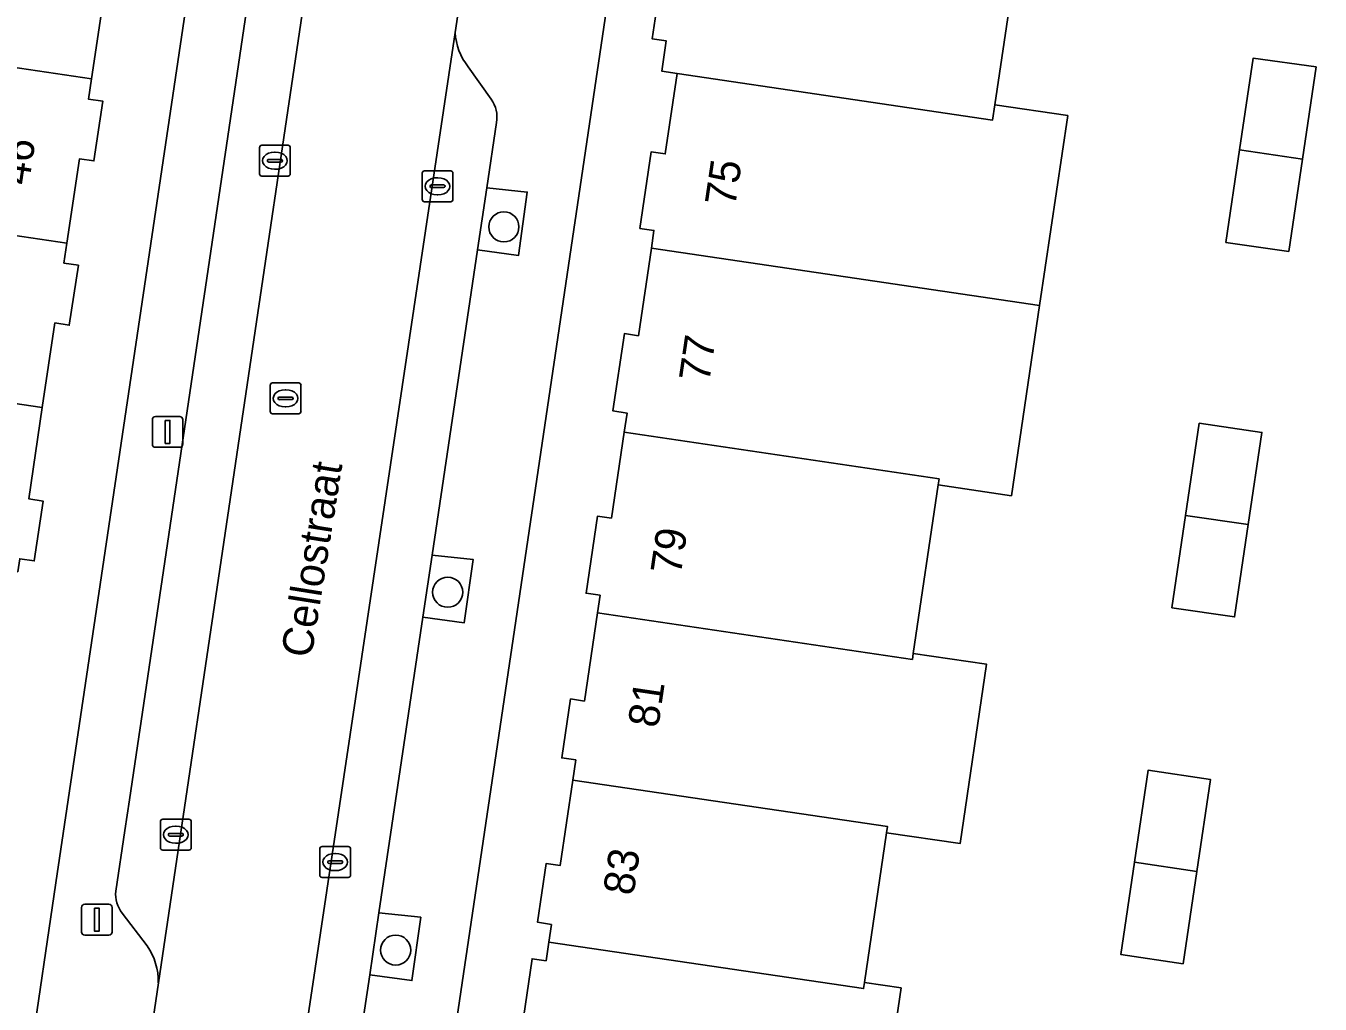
# Model space of a CAD drawing. Extents: x 164148 to 165261, y 382513 to 383432.
# Drawn here: x 164386.93 to 164428.99, y 382927.78 to 382959.57 of the extents above; entities that cross this region are included whole.
import ezdxf

# ---------------------------------------------------------------- set-up
doc = ezdxf.new("R2010")
doc.units = 0
for name, color, linetype in [('IMGEO_Boom', 7, 'Continuous'), ('IMGEO_Erf', 7, 'Continuous'), ('IMGEO_Groenvoorziening', 7, 'Continuous'), ('IMGEO_Kolk', 7, 'Continuous'), ('IMGEO_Lichtmast', 7, 'Continuous'), ('IMGEO_Openbare_ruimte_label', 7, 'Continuous'), ('IMGEO_Pand', 7, 'Continuous'), ('IMGEO_Pand_nummerreeks', 7, 'Continuous'), ('IMGEO_Parkeervlak_open', 7, 'Continuous'), ('IMGEO_Rijbaan_lokaal_open', 7, 'Continuous'), ('IMGEO_Rioolput', 7, 'Continuous'), ('IMGEO_Voetpad_open', 7, 'Continuous')]:
    doc.layers.add(name, color=color, linetype=linetype)

msp = doc.modelspace()

# ---------------------------------------------------------------- linework, layer by layer
at = {"layer": 'IMGEO_Boom'}
for centre in [(164402.46, 382953.036), (164400.635, 382941.165), (164398.944, 382929.538)]:
    msp.add_circle(centre, 0.489, dxfattribs=at)
at = {"layer": 'IMGEO_Erf'}
for points in [[(164386.768, 382924.065), (164387.061, 382926.045), (164387.902, 382931.724), (164393.467, 382969.194), (164386.248, 382970.282)], [(164385.848, 382967.079), (164390.338, 382966.42), (164389.758, 382962.536), (164390.227, 382962.469), (164389.942, 382960.525), (164389.467, 382960.594), (164389.057, 382957.848), (164388.959, 382957.188), (164389.428, 382957.119), (164389.14, 382955.178), (164388.669, 382955.248), (164388.259, 382952.508), (164388.162, 382951.861), (164388.632, 382951.789), (164388.334, 382949.842), (164387.872, 382949.916), (164387.461, 382947.169), (164387.018, 382944.201), (164387.488, 382944.128), (164387.199, 382942.18), (164386.727, 382942.253)], [(164419.288, 382962.906), (164418.415, 382957.004), (164420.787, 382956.653), (164419.872, 382950.476), (164418.957, 382944.298), (164416.574, 382944.65), (164415.764, 382939.179), (164418.147, 382938.826), (164417.284, 382932.998), (164414.9, 382933.351), (164414.179, 382928.484), (164415.369, 382928.308), (164414.544, 382922.733)], [(164403.093, 382927.341), (164403.379, 382929.257), (164403.833, 382929.19), (164403.923, 382929.8), (164404.006, 382930.366), (164403.553, 382930.447), (164403.838, 382932.357), (164404.291, 382932.291), (164404.7, 382935.064), (164404.796, 382935.716), (164404.343, 382935.784), (164404.628, 382937.7), (164405.079, 382937.631), (164405.503, 382940.497), (164405.587, 382941.066), (164405.132, 382941.132), (164405.507, 382943.641), (164405.957, 382943.574), (164406.37, 382946.365), (164406.462, 382946.988), (164406.006, 382947.057), (164406.38, 382949.567), (164406.833, 382949.501), (164407.253, 382952.345), (164407.338, 382952.921), (164406.884, 382952.988), (164407.25, 382955.475), (164407.705, 382955.408), (164408.091, 382958.021), (164407.589, 382958.097), (164407.736, 382959.075), (164407.281, 382959.143), (164407.67, 382961.751)]]:
    msp.add_lwpolyline(points, dxfattribs=at)
for points in [[(164455.128, 382958.161), (164406.562, 382965.305), (164395.217, 382888.733), (164443.704, 382881.759), (164444.09, 382883.266), (164444.484, 382885.938)], [(164425.925, 382952.531), (164426.369, 382955.541), (164426.808, 382958.517), (164428.857, 382958.234), (164428.412, 382955.238), (164427.968, 382952.241)], [(164426.651, 382943.361), (164426.207, 382940.363), (164424.173, 382940.661), (164424.616, 382943.662), (164425.058, 382946.655), (164427.096, 382946.358)], [(164422.511, 382929.391), (164422.953, 382932.391), (164423.394, 382935.382), (164425.424, 382935.085), (164424.98, 382932.091), (164424.535, 382929.096)]]:
    msp.add_lwpolyline(points, close=True, dxfattribs=at)
at = {"layer": 'IMGEO_Groenvoorziening'}
for points in [[(164401.902, 382954.305), (164401.602, 382952.29), (164402.936, 382952.107), (164403.221, 382954.164)], [(164400.128, 382942.373), (164399.829, 382940.36), (164401.173, 382940.175), (164401.458, 382942.232)], [(164398.4, 382930.752), (164398.1, 382928.736), (164399.474, 382928.549), (164399.759, 382930.606)]]:
    msp.add_lwpolyline(points, close=True, dxfattribs=at)
at = {"layer": 'IMGEO_Kolk'}
for p, q in [((164394.519, 382954.76), (164394.519, 382955.612)), ((164394.594, 382955.686), (164395.446, 382955.686)), ((164395.52, 382955.612), (164395.52, 382954.76)), ((164394.778, 382955.18), (164394.778, 382955.192)), ((164395.216, 382955.143), (164394.818, 382955.143)), ((164394.821, 382955.229), (164395.219, 382955.229)), ((164395.007, 382955.466), (164395.032, 382955.466)), ((164395.262, 382955.192), (164395.262, 382955.18)), ((164395.446, 382954.686), (164394.594, 382954.686)), ((164395.03, 382954.906), (164395.005, 382954.906)), ((164399.805, 382953.928), (164399.805, 382954.78)), ((164399.88, 382954.854), (164400.732, 382954.854)), ((164400.293, 382954.634), (164400.318, 382954.634)), ((164400.806, 382954.78), (164400.806, 382953.928)), ((164400.064, 382954.348), (164400.064, 382954.36)), ((164400.502, 382954.311), (164400.104, 382954.311)), ((164400.107, 382954.397), (164400.505, 382954.397)), ((164400.548, 382954.36), (164400.548, 382954.348)), ((164400.732, 382953.854), (164399.88, 382953.854)), ((164400.316, 382954.074), (164400.291, 382954.074)), ((164391.298, 382932.862), (164391.298, 382933.714)), ((164391.373, 382933.788), (164392.225, 382933.788)), ((164392.299, 382933.714), (164392.299, 382932.862)), ((164391.557, 382933.282), (164391.557, 382933.294)), ((164391.995, 382933.245), (164391.597, 382933.245)), ((164391.6, 382933.331), (164391.998, 382933.331)), ((164391.786, 382933.568), (164391.811, 382933.568)), ((164392.041, 382933.294), (164392.041, 382933.282)), ((164392.225, 382932.788), (164391.373, 382932.788)), ((164391.809, 382933.008), (164391.784, 382933.008)), ((164396.477, 382931.973), (164396.477, 382932.825)), ((164396.552, 382932.899), (164397.404, 382932.899)), ((164397.478, 382932.825), (164397.478, 382931.973)), ((164396.736, 382932.393), (164396.736, 382932.405)), ((164397.174, 382932.356), (164396.776, 382932.356)), ((164396.779, 382932.442), (164397.177, 382932.442)), ((164396.965, 382932.679), (164396.99, 382932.679)), ((164397.22, 382932.405), (164397.22, 382932.393)), ((164396.988, 382932.119), (164396.963, 382932.119)), ((164397.404, 382931.899), (164396.552, 382931.899))]:
    msp.add_line(p, q, dxfattribs=at)
for points in [[(164394.519, 382954.76), (164394.519, 382955.612)], [(164394.594, 382955.686), (164395.446, 382955.686)], [(164395.52, 382955.612), (164395.52, 382954.76)], [(164395.446, 382954.686), (164394.594, 382954.686)], [(164399.805, 382953.928), (164399.805, 382954.78)], [(164399.88, 382954.854), (164400.732, 382954.854)], [(164400.806, 382954.78), (164400.806, 382953.928)], [(164400.732, 382953.854), (164399.88, 382953.854)], [(164391.298, 382932.862), (164391.298, 382933.714)], [(164391.373, 382933.788), (164392.225, 382933.788)], [(164392.299, 382933.714), (164392.299, 382932.862)], [(164392.225, 382932.788), (164391.373, 382932.788)], [(164396.477, 382931.973), (164396.477, 382932.825)], [(164396.552, 382932.899), (164397.404, 382932.899)], [(164397.478, 382932.825), (164397.478, 382931.973)], [(164397.404, 382931.899), (164396.552, 382931.899)]]:
    msp.add_lwpolyline(points, dxfattribs=at)
for centre, radius, start, end in [((164394.596, 382955.61), 0.0765, 91.552, 178.448), ((164394.596, 382955.61), 0.0765, 91.552, 178.448), ((164395.444, 382955.61), 0.0765, 1.552, 88.448), ((164395.444, 382955.61), 0.0765, 1.552, 88.448), ((164394.818, 382955.189), 0.0403, 85.8775, 175.7526), ((164394.815, 382955.179), 0.0366, 178.938, 274.7102), ((164395.219, 382955.186), 0.043, 264.8664, 352.4533), ((164395.223, 382955.191), 0.0386, 1.7309, 96.639), ((164394.596, 382954.762), 0.0765, 181.552, 268.448), ((164394.596, 382954.762), 0.0765, 181.552, 268.448), ((164395.444, 382954.762), 0.0765, 271.552, 358.448), ((164395.444, 382954.762), 0.0765, 271.552, 358.448), ((164399.882, 382954.778), 0.0765, 91.552, 178.448), ((164399.882, 382954.778), 0.0765, 91.552, 178.448), ((164400.73, 382954.778), 0.0765, 1.552, 88.448), ((164400.73, 382954.778), 0.0765, 1.552, 88.448), ((164400.104, 382954.357), 0.0403, 85.8775, 175.7526), ((164400.101, 382954.347), 0.0366, 178.938, 274.7102), ((164400.505, 382954.354), 0.043, 264.8664, 352.4533), ((164400.509, 382954.359), 0.0386, 1.7309, 96.639), ((164399.882, 382953.93), 0.0765, 181.552, 268.448), ((164399.882, 382953.93), 0.0765, 181.552, 268.448), ((164400.73, 382953.93), 0.0765, 271.552, 358.448), ((164400.73, 382953.93), 0.0765, 271.552, 358.448), ((164391.375, 382933.712), 0.0765, 91.552, 178.448), ((164391.375, 382933.712), 0.0765, 91.552, 178.448), ((164392.223, 382933.712), 0.0765, 1.552, 88.448), ((164392.223, 382933.712), 0.0765, 1.552, 88.448), ((164391.597, 382933.291), 0.0403, 85.8775, 175.7526), ((164391.594, 382933.281), 0.0366, 178.938, 274.7102), ((164391.998, 382933.288), 0.043, 264.8664, 352.4533), ((164392.002, 382933.293), 0.0386, 1.7309, 96.639), ((164391.375, 382932.864), 0.0765, 181.552, 268.448), ((164391.375, 382932.864), 0.0765, 181.552, 268.448), ((164392.223, 382932.864), 0.0765, 271.552, 358.448), ((164392.223, 382932.864), 0.0765, 271.552, 358.448), ((164396.554, 382932.823), 0.0765, 91.552, 178.448), ((164396.554, 382932.823), 0.0765, 91.552, 178.448), ((164397.402, 382932.823), 0.0765, 1.552, 88.448), ((164397.402, 382932.823), 0.0765, 1.552, 88.448), ((164396.776, 382932.402), 0.0403, 85.8775, 175.7526), ((164396.773, 382932.392), 0.0366, 178.938, 274.7102), ((164397.177, 382932.399), 0.043, 264.8664, 352.4533), ((164397.181, 382932.404), 0.0386, 1.7309, 96.639), ((164396.554, 382931.975), 0.0765, 181.552, 268.448), ((164396.554, 382931.975), 0.0765, 181.552, 268.448), ((164397.402, 382931.975), 0.0765, 271.552, 358.448), ((164397.402, 382931.975), 0.0765, 271.552, 358.448)]:
    msp.add_arc(centre, radius, start, end, dxfattribs=at)
for centre, major_axis, ratio, start_param, end_param in [((164395.006, 382955.186), (-0.387, 0.002), 0.722429, 4.712389, 7.853982), ((164395.031, 382955.186), (-0.39, 0.002), 0.717154, 1.570796, 4.712389), ((164400.292, 382954.354), (-0.387, 0.002), 0.722429, 4.712389, 7.853982), ((164400.317, 382954.354), (-0.39, 0.002), 0.717154, 1.570796, 4.712389), ((164391.785, 382933.288), (-0.387, 0.002), 0.722429, 4.712389, 7.853982), ((164391.81, 382933.288), (-0.39, 0.002), 0.717154, 1.570796, 4.712389), ((164396.964, 382932.399), (-0.387, 0.002), 0.722429, 4.712389, 7.853982), ((164396.989, 382932.399), (-0.39, 0.002), 0.717154, 1.570796, 4.712389)]:
    msp.add_ellipse(centre, major_axis=major_axis, ratio=ratio, start_param=start_param, end_param=end_param, dxfattribs=at)
at = {"layer": 'IMGEO_Lichtmast'}
for p, q in [((164391.038, 382945.973), (164391.038, 382946.773)), ((164391.038, 382946.773), (164391.038, 382945.973)), ((164391.138, 382946.873), (164391.928, 382946.873)), ((164391.928, 382946.873), (164391.138, 382946.873)), ((164392.028, 382946.773), (164392.028, 382945.973)), ((164392.028, 382945.973), (164392.028, 382946.773)), ((164391.928, 382945.873), (164391.138, 382945.873)), ((164391.138, 382945.873), (164391.928, 382945.873)), ((164388.737, 382930.126), (164388.737, 382930.926)), ((164388.737, 382930.926), (164388.737, 382930.126)), ((164388.837, 382931.026), (164389.627, 382931.026)), ((164389.627, 382931.026), (164388.837, 382931.026)), ((164389.727, 382930.926), (164389.727, 382930.126)), ((164389.727, 382930.126), (164389.727, 382930.926)), ((164389.627, 382930.026), (164388.837, 382930.026)), ((164388.837, 382930.026), (164389.627, 382930.026))]:
    msp.add_line(p, q, dxfattribs=at)
for points in [[(164391.458, 382946.748), (164391.608, 382946.748), (164391.608, 382945.998), (164391.458, 382945.998), (164391.458, 382946.748)], [(164389.157, 382930.901), (164389.307, 382930.901), (164389.307, 382930.151), (164389.157, 382930.151), (164389.157, 382930.901)]]:
    msp.add_lwpolyline(points, dxfattribs=at)
for centre, start, end in [((164391.138, 382946.773), 90, 180), ((164391.138, 382946.773), 90, 180), ((164391.928, 382946.773), 0, 90), ((164391.928, 382946.773), 360, 90), ((164391.138, 382945.973), 180, 270), ((164391.138, 382945.973), 180, 270), ((164391.928, 382945.973), 270, 0), ((164391.928, 382945.973), 270, 0), ((164388.837, 382930.926), 90, 180), ((164388.837, 382930.926), 90, 180), ((164389.627, 382930.926), 0, 90), ((164389.627, 382930.926), 360, 90), ((164388.837, 382930.126), 180, 270), ((164388.837, 382930.126), 180, 270), ((164389.627, 382930.126), 270, 0), ((164389.627, 382930.126), 270, 0)]:
    msp.add_arc(centre, 0.1, start, end, dxfattribs=at)
at = {"layer": 'IMGEO_Pand'}
for points in [[(164389.758, 382962.536), (164390.338, 382966.42), (164385.848, 382967.079), (164385.387, 382963.963), (164384.358, 382964.12), (164379.624, 382964.842), (164378.809, 382959.364), (164389.057, 382957.848), (164389.467, 382960.594), (164389.942, 382960.525), (164390.227, 382962.469)], [(164419.288, 382962.906), (164408.545, 382964.496), (164408.125, 382961.681), (164407.67, 382961.751), (164407.281, 382959.143), (164407.736, 382959.075), (164407.589, 382958.097), (164408.091, 382958.021), (164418.341, 382956.503), (164418.415, 382957.004)], [(164389.428, 382957.119), (164388.959, 382957.188), (164389.057, 382957.848), (164378.809, 382959.364), (164378.014, 382954.022), (164388.259, 382952.508), (164388.669, 382955.248), (164389.14, 382955.178)], [(164428.857, 382958.234), (164426.808, 382958.517), (164426.369, 382955.541), (164428.412, 382955.238)], [(164420.787, 382956.653), (164418.415, 382957.004), (164418.341, 382956.503), (164408.091, 382958.021), (164407.705, 382955.408), (164407.25, 382955.475), (164406.884, 382952.988), (164407.338, 382952.921), (164407.253, 382952.345), (164419.872, 382950.476)], [(164428.412, 382955.238), (164426.369, 382955.541), (164425.925, 382952.531), (164427.968, 382952.241)], [(164388.162, 382951.861), (164388.259, 382952.508), (164378.014, 382954.022), (164377.241, 382948.828), (164376.053, 382949.005), (164376.031, 382948.861), (164387.461, 382947.169), (164387.872, 382949.916), (164388.334, 382949.842), (164388.632, 382951.789)], [(164419.872, 382950.476), (164407.253, 382952.345), (164406.833, 382949.501), (164406.38, 382949.567), (164406.006, 382947.057), (164406.462, 382946.988), (164406.37, 382946.365), (164416.603, 382944.848), (164416.574, 382944.65), (164418.957, 382944.298)], [(164387.461, 382947.169), (164376.031, 382948.861), (164375.257, 382943.667), (164374.061, 382943.851), (164374.038, 382943.697), (164386.664, 382941.829), (164386.727, 382942.253), (164387.199, 382942.18), (164387.488, 382944.128), (164387.018, 382944.201)], [(164427.096, 382946.358), (164425.058, 382946.655), (164424.616, 382943.662), (164426.651, 382943.361)], [(164416.574, 382944.65), (164416.603, 382944.848), (164406.37, 382946.365), (164405.957, 382943.574), (164405.507, 382943.641), (164405.132, 382941.132), (164405.587, 382941.066), (164405.503, 382940.497), (164415.735, 382938.981), (164415.764, 382939.179)], [(164426.651, 382943.361), (164424.616, 382943.662), (164424.173, 382940.661), (164426.207, 382940.363)], [(164418.147, 382938.826), (164415.764, 382939.179), (164415.735, 382938.981), (164405.503, 382940.497), (164405.079, 382937.631), (164404.628, 382937.7), (164404.343, 382935.784), (164404.796, 382935.716), (164404.7, 382935.064), (164414.929, 382933.549), (164414.9, 382933.351), (164417.284, 382932.998)], [(164425.424, 382935.085), (164423.394, 382935.382), (164422.953, 382932.391), (164424.98, 382932.091)], [(164414.9, 382933.351), (164414.929, 382933.549), (164404.7, 382935.064), (164404.291, 382932.291), (164403.838, 382932.357), (164403.553, 382930.447), (164404.006, 382930.366), (164403.923, 382929.8), (164414.15, 382928.286), (164414.179, 382928.484)], [(164424.98, 382932.091), (164422.953, 382932.391), (164422.511, 382929.391), (164424.535, 382929.096)], [(164415.369, 382928.308), (164414.179, 382928.484), (164414.15, 382928.286), (164403.923, 382929.8), (164403.833, 382929.19), (164403.379, 382929.257), (164403.093, 382927.341), (164403.549, 382927.272), (164403.128, 382924.422), (164414.544, 382922.733)]]:
    msp.add_lwpolyline(points, close=True, dxfattribs=at)
at = {"layer": 'IMGEO_Parkeervlak_open'}
for points in [[(164396.236, 382962.229), (164396.356, 382963.04), (164396.938, 382966.961), (164395.156, 382967.237), (164390.293, 382934.417), (164390.146, 382933.429), (164389.851, 382931.455)], [(164391.231, 382928.476), (164396.236, 382962.229)], [(164400.876, 382959.355), (164395.748, 382925.028), (164390.296, 382888.433)], [(164402.044, 382957.182), (164401.299, 382958.237)], [(164397.524, 382924.861), (164398.1, 382928.736), (164398.4, 382930.752), (164399.829, 382940.36), (164400.128, 382942.373), (164401.602, 382952.29), (164401.902, 382954.305), (164402.218, 382956.43)], [(164390.059, 382930.735), (164390.866, 382929.675)]]:
    msp.add_lwpolyline(points, dxfattribs=at)
for centre, radius, start, end in [((164402.882, 382959.475), 2.01, 183.4218, 218.0268), ((164401.287, 382956.611), 0.948, 349.0035, 37.0525), ((164390.797, 382931.338), 0.953, 172.9536, 219.2732), ((164389.2, 382928.513), 2.031, 358.9605, 34.9022)]:
    msp.add_arc(centre, radius, start, end, dxfattribs=at)
at = {"layer": 'IMGEO_Rijbaan_lokaal_open'}
msp.add_lwpolyline([(164400.876, 382959.355), (164401.178, 382961.379), (164396.236, 382962.229), (164391.231, 382928.476), (164390.809, 382925.629), (164389.611, 382917.573), (164389.603, 382917.523), (164385.388, 382889.174), (164385.323, 382888.74), (164383.455, 382876.131), (164383.436, 382876.014), (164388.332, 382875.297), (164388.347, 382875.416), (164390.241, 382888.06), (164390.296, 382888.433), (164395.748, 382925.028)], close=True, dxfattribs=at)
at = {"layer": 'IMGEO_Rioolput'}
for p, q in [((164394.941, 382947.965), (164395.793, 382947.965)), ((164394.866, 382947.039), (164394.866, 382947.891)), ((164395.168, 382947.508), (164395.566, 382947.508)), ((164395.354, 382947.745), (164395.379, 382947.745)), ((164395.867, 382947.891), (164395.867, 382947.039)), ((164395.125, 382947.459), (164395.125, 382947.471)), ((164395.563, 382947.422), (164395.165, 382947.422)), ((164395.377, 382947.185), (164395.352, 382947.185)), ((164395.609, 382947.471), (164395.609, 382947.459)), ((164395.793, 382946.965), (164394.941, 382946.965))]:
    msp.add_line(p, q, dxfattribs=at)
for points in [[(164394.941, 382947.965), (164395.793, 382947.965)], [(164394.866, 382947.039), (164394.866, 382947.891)], [(164395.867, 382947.891), (164395.867, 382947.039)], [(164395.793, 382946.965), (164394.941, 382946.965)]]:
    msp.add_lwpolyline(points, dxfattribs=at)
for centre, radius, start, end in [((164394.943, 382947.889), 0.0765, 91.552, 178.448), ((164394.943, 382947.889), 0.0765, 91.552, 178.448), ((164395.791, 382947.889), 0.0765, 1.552, 88.448), ((164395.791, 382947.889), 0.0765, 1.552, 88.448), ((164395.165, 382947.468), 0.0403, 85.8775, 175.7526), ((164395.57, 382947.47), 0.0386, 1.7309, 96.639), ((164395.162, 382947.458), 0.0366, 178.938, 274.7102), ((164395.566, 382947.465), 0.043, 264.8664, 352.4533), ((164394.943, 382947.041), 0.0765, 181.552, 268.448), ((164394.943, 382947.041), 0.0765, 181.552, 268.448), ((164395.791, 382947.041), 0.0765, 271.552, 358.448), ((164395.791, 382947.041), 0.0765, 271.552, 358.448)]:
    msp.add_arc(centre, radius, start, end, dxfattribs=at)
for centre, major_axis, ratio, start_param, end_param in [((164395.353, 382947.465), (-0.387, 0.002), 0.722429, 4.712389, 7.853982), ((164395.378, 382947.465), (-0.39, 0.002), 0.717154, 1.570796, 4.712389)]:
    msp.add_ellipse(centre, major_axis=major_axis, ratio=ratio, start_param=start_param, end_param=end_param, dxfattribs=at)
at = {"layer": 'IMGEO_Voetpad_open'}
for points in [[(164331.556, 382883.173), (164332.58, 382889.948), (164333.508, 382896.089), (164333.774, 382897.977), (164334.647, 382897.854), (164343.748, 382959.071), (164346.307, 382976.27), (164346.897, 382980.236), (164351.168, 383008.935), (164353.396, 383008.625), (164396.201, 383002.256), (164398.318, 383001.938), (164394.057, 382973.175), (164393.467, 382969.194), (164387.902, 382931.724), (164387.061, 382926.045), (164386.768, 382924.065), (164386.181, 382920.095), (164381.848, 382890.825), (164381.663, 382889.579), (164382.566, 382889.449), (164382.495, 382888.849), (164381.579, 382882.687), (164380.573, 382875.921)], [(164389.851, 382931.455), (164390.146, 382933.429), (164390.293, 382934.417), (164395.156, 382967.237), (164396.45, 382975.965), (164399.098, 382993.834)], [(164391.121, 382874.384), (164392.122, 382881.133), (164393.036, 382887.297), (164393.114, 382888.054), (164395.078, 382887.796), (164395.217, 382888.733), (164406.562, 382965.305)], [(164401.312, 382962.274), (164401.178, 382961.379), (164400.876, 382959.355)], [(164401.299, 382958.237), (164402.044, 382957.182)], [(164402.218, 382956.43), (164401.902, 382954.305), (164403.221, 382954.164), (164402.936, 382952.107), (164401.602, 382952.29), (164400.128, 382942.373), (164401.458, 382942.232), (164401.173, 382940.175), (164399.829, 382940.36), (164398.4, 382930.752), (164399.759, 382930.606), (164399.474, 382928.549), (164398.1, 382928.736), (164397.524, 382924.861)], [(164390.866, 382929.675), (164390.059, 382930.735)], [(164389.603, 382917.523), (164389.611, 382917.573), (164388.519, 382917.758), (164389.722, 382925.788), (164390.809, 382925.629), (164391.231, 382928.476)]]:
    msp.add_lwpolyline(points, dxfattribs=at)
for centre, radius, start, end in [((164402.882, 382959.475), 2.01, 183.4218, 218.0268), ((164401.287, 382956.611), 0.948, 349.0035, 37.0525), ((164390.797, 382931.338), 0.953, 172.9536, 219.2732), ((164389.2, 382928.513), 2.031, 358.9605, 34.9022)]:
    msp.add_arc(centre, radius, start, end, dxfattribs=at)

# ---------------------------------------------------------------- texts
at = {"layer": 'IMGEO_Openbare_ruimte_label'}
msp.add_text('Cellostraat', height=1, rotation=80.9142, dxfattribs=at).set_placement((164396.203, 382939.002))
at = {"layer": 'IMGEO_Pand_nummerreeks'}
for s, rotation, p in [('46', 81.4861, (164387.02, 382954.363)), ('75', 81.5949, (164409.975, 382953.668)), ('77', 81.6006, (164409.132, 382947.959)), ('79', 81.5835, (164408.208, 382941.703)), ('81', 81.5892, (164407.473, 382936.731)), ('83', 81.6121, (164406.67, 382931.285))]:
    msp.add_text(s, height=1, rotation=rotation, dxfattribs=at).set_placement(p)

doc.saveas('drawing.dxf')
